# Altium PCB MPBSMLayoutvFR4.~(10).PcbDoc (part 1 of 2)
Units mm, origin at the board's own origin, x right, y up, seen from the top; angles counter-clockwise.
Board outline 131.7 x 110.39 mm, 4 copper layers (Top Layer, Power, GroundPlane, Bottom Layer), stack 2.286 mm thick; 156 components, 77 nets, 429 pads, 117 vias.
Unrouted connection lines stored in the file: 25.
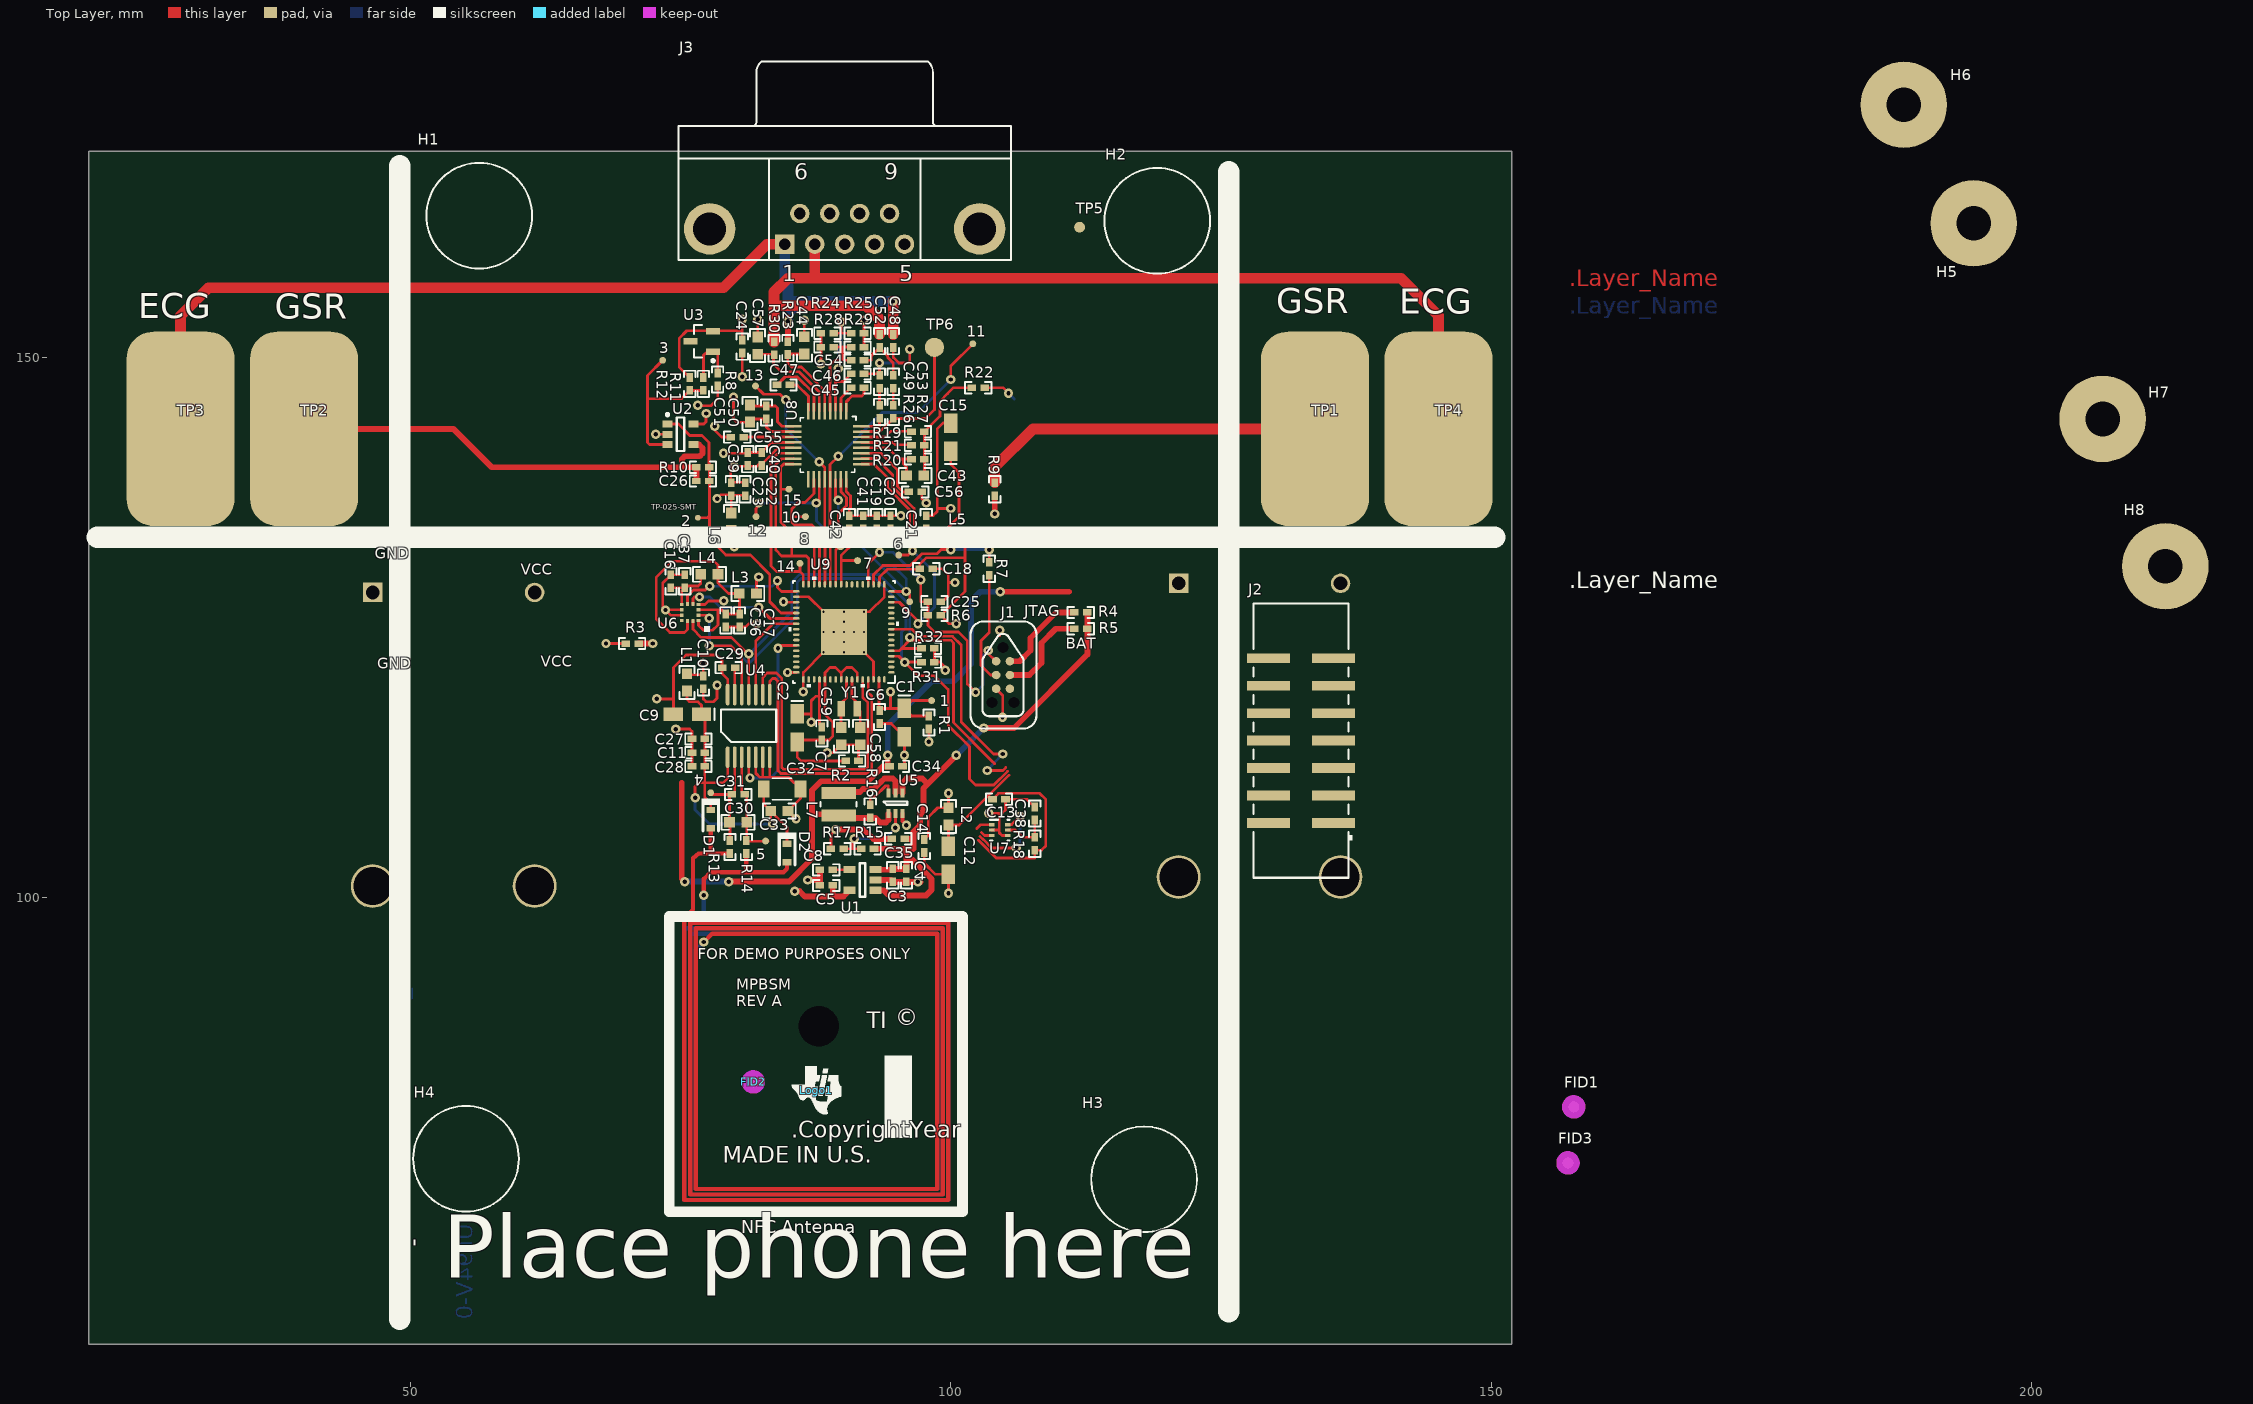
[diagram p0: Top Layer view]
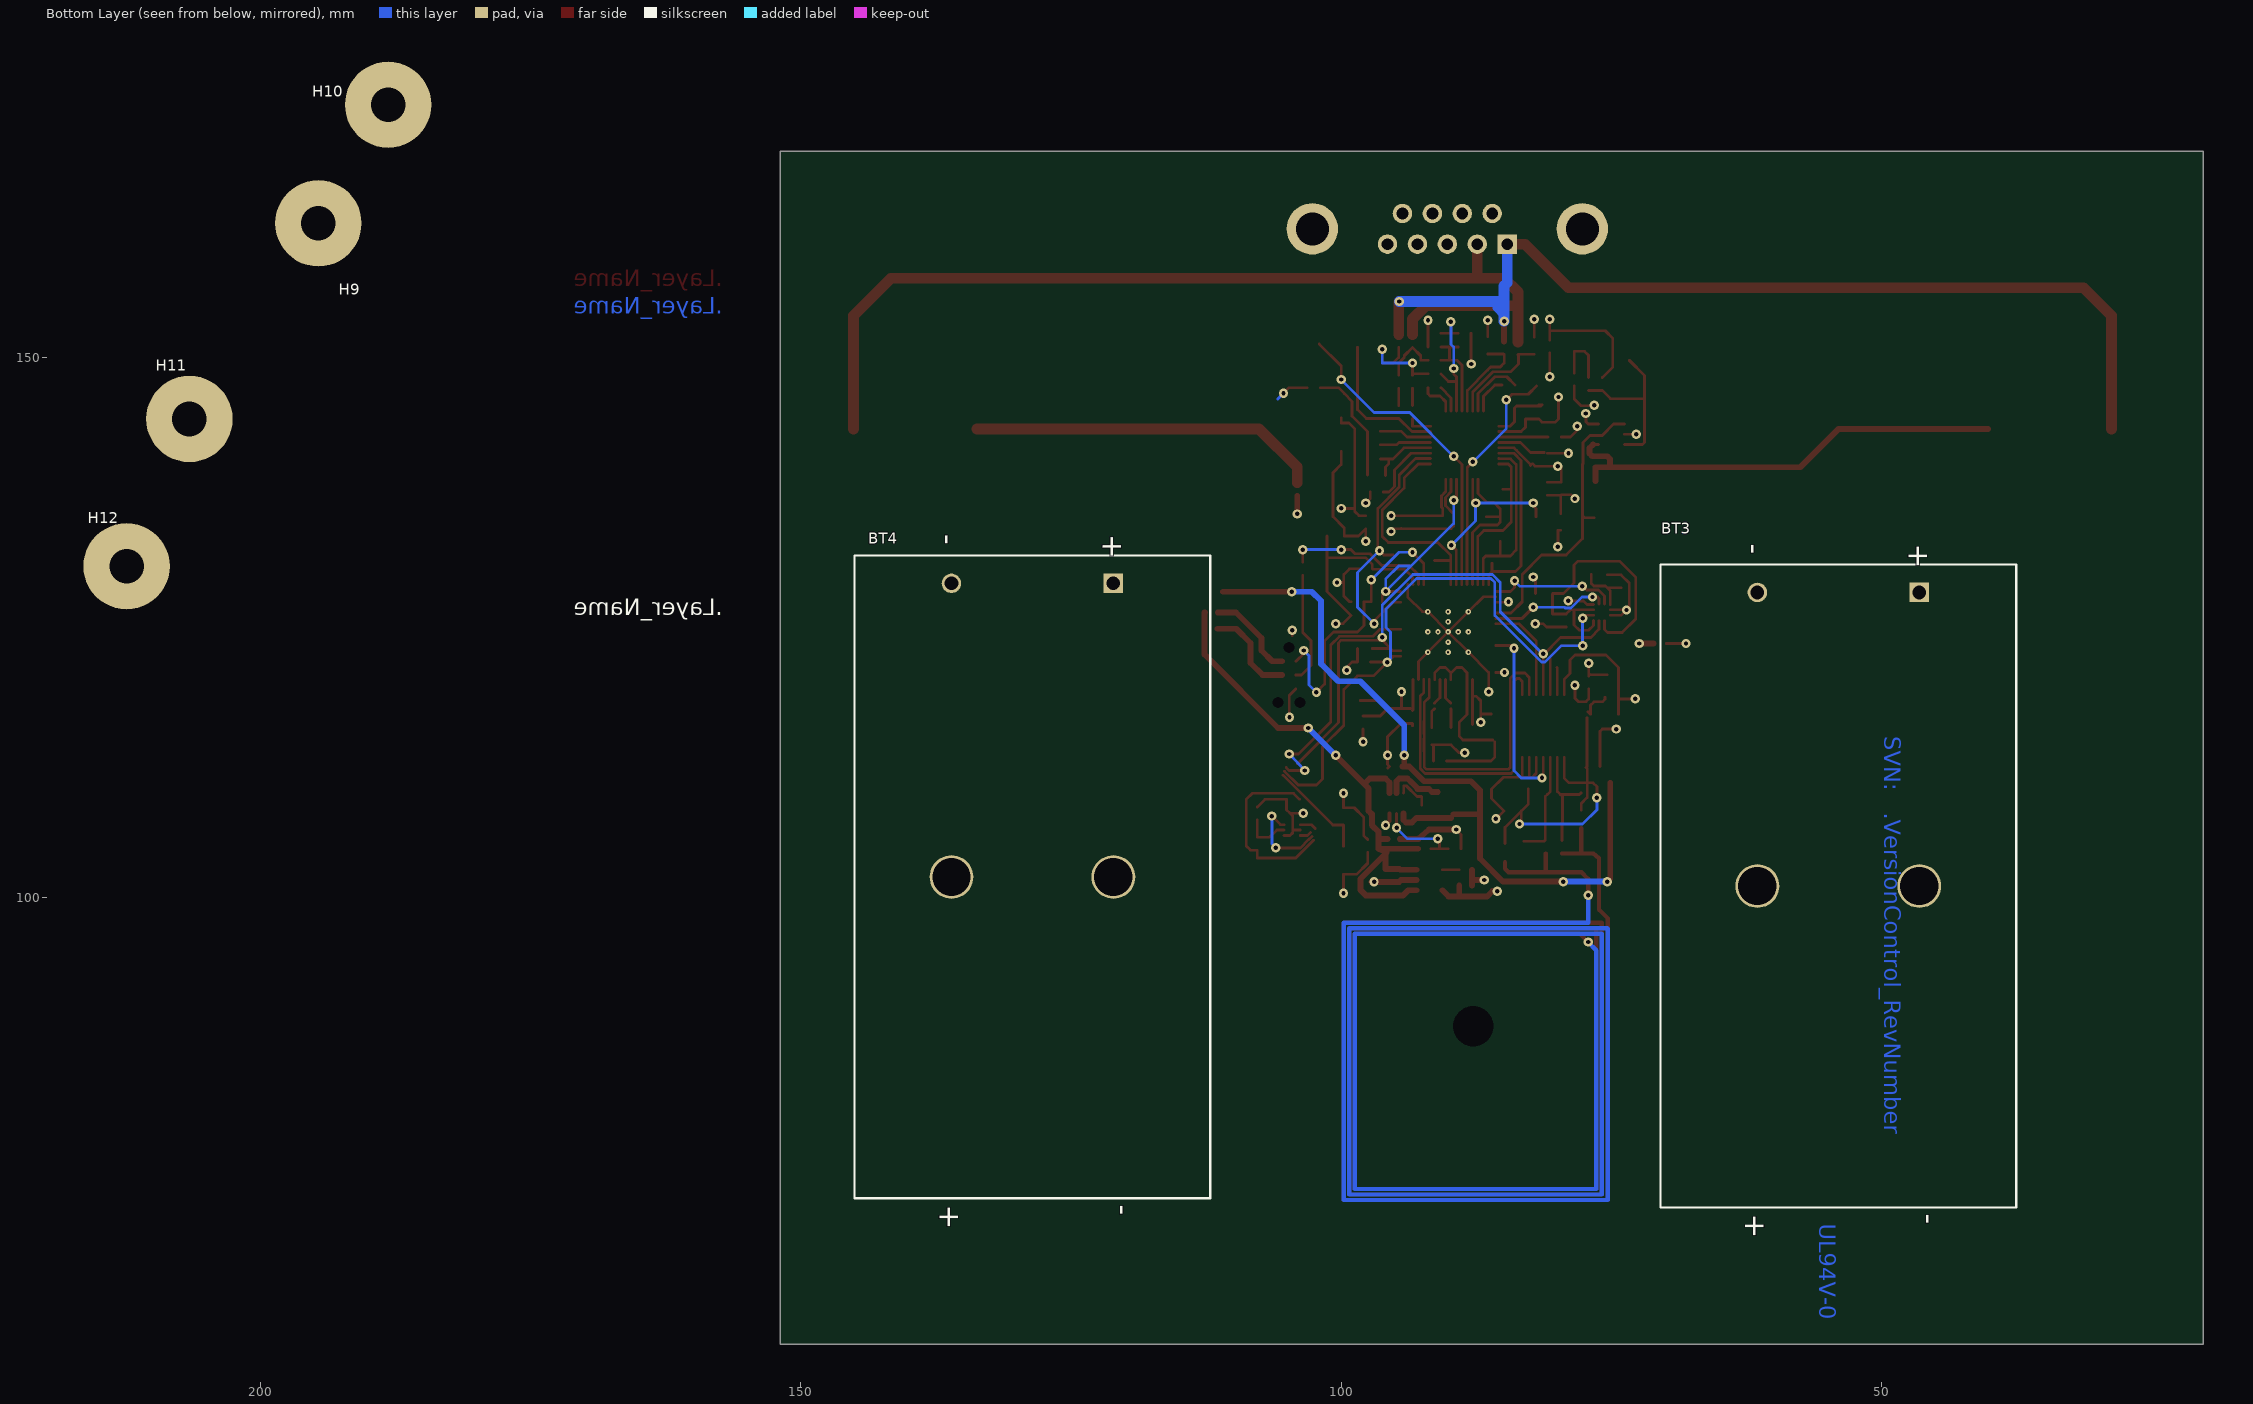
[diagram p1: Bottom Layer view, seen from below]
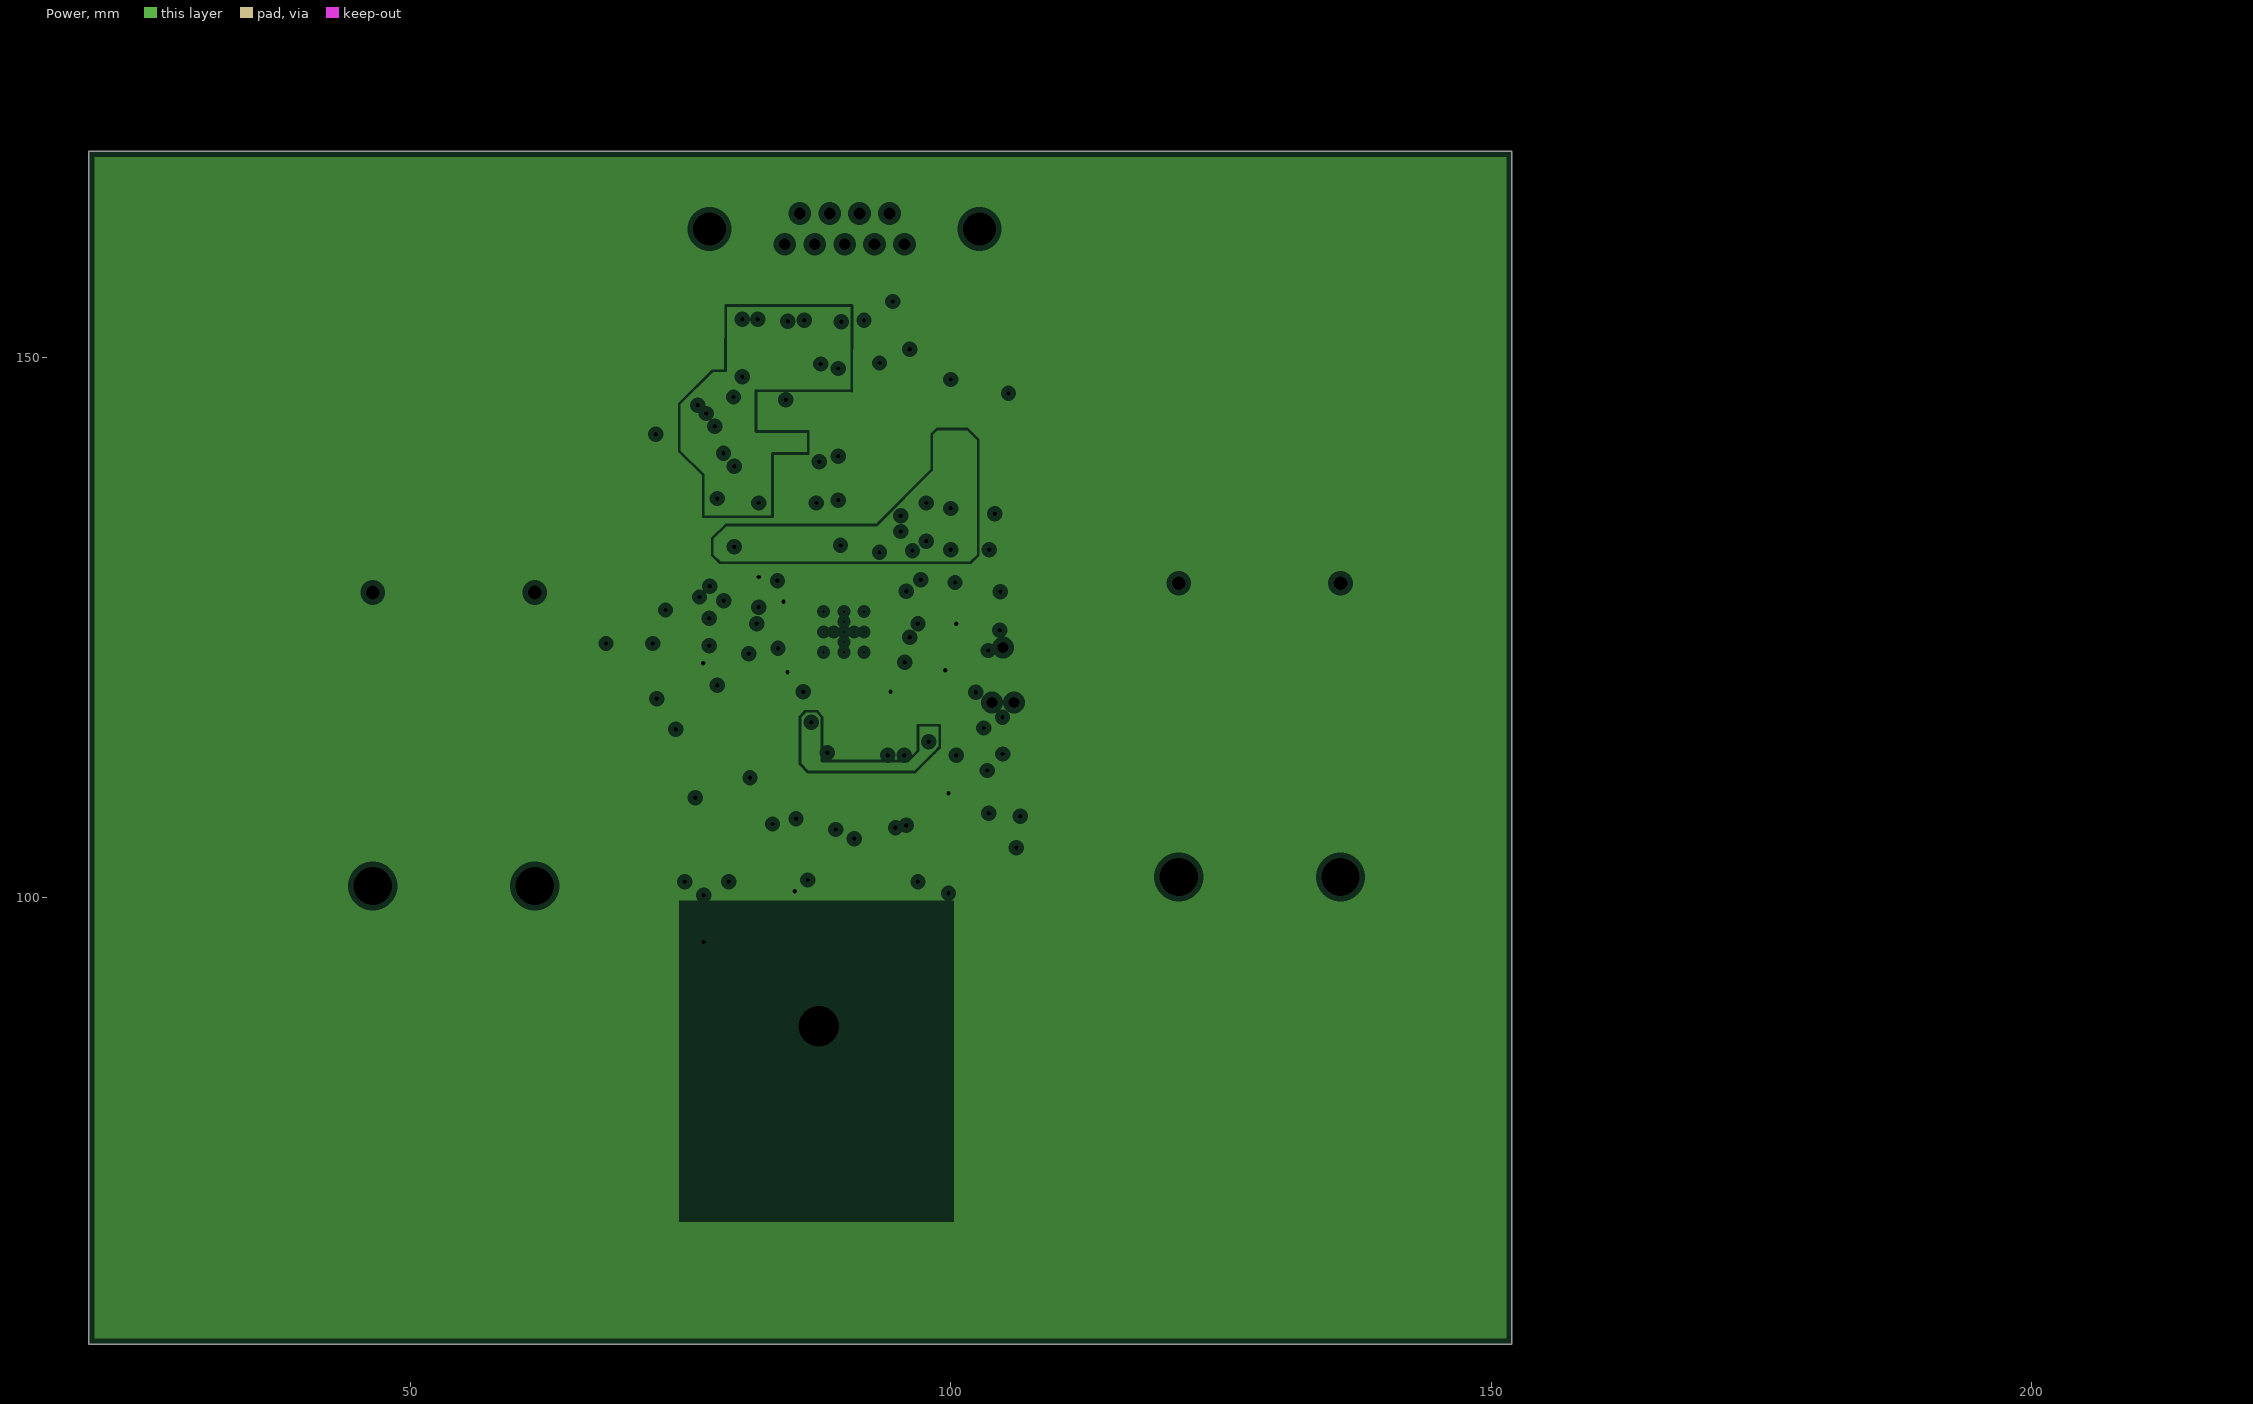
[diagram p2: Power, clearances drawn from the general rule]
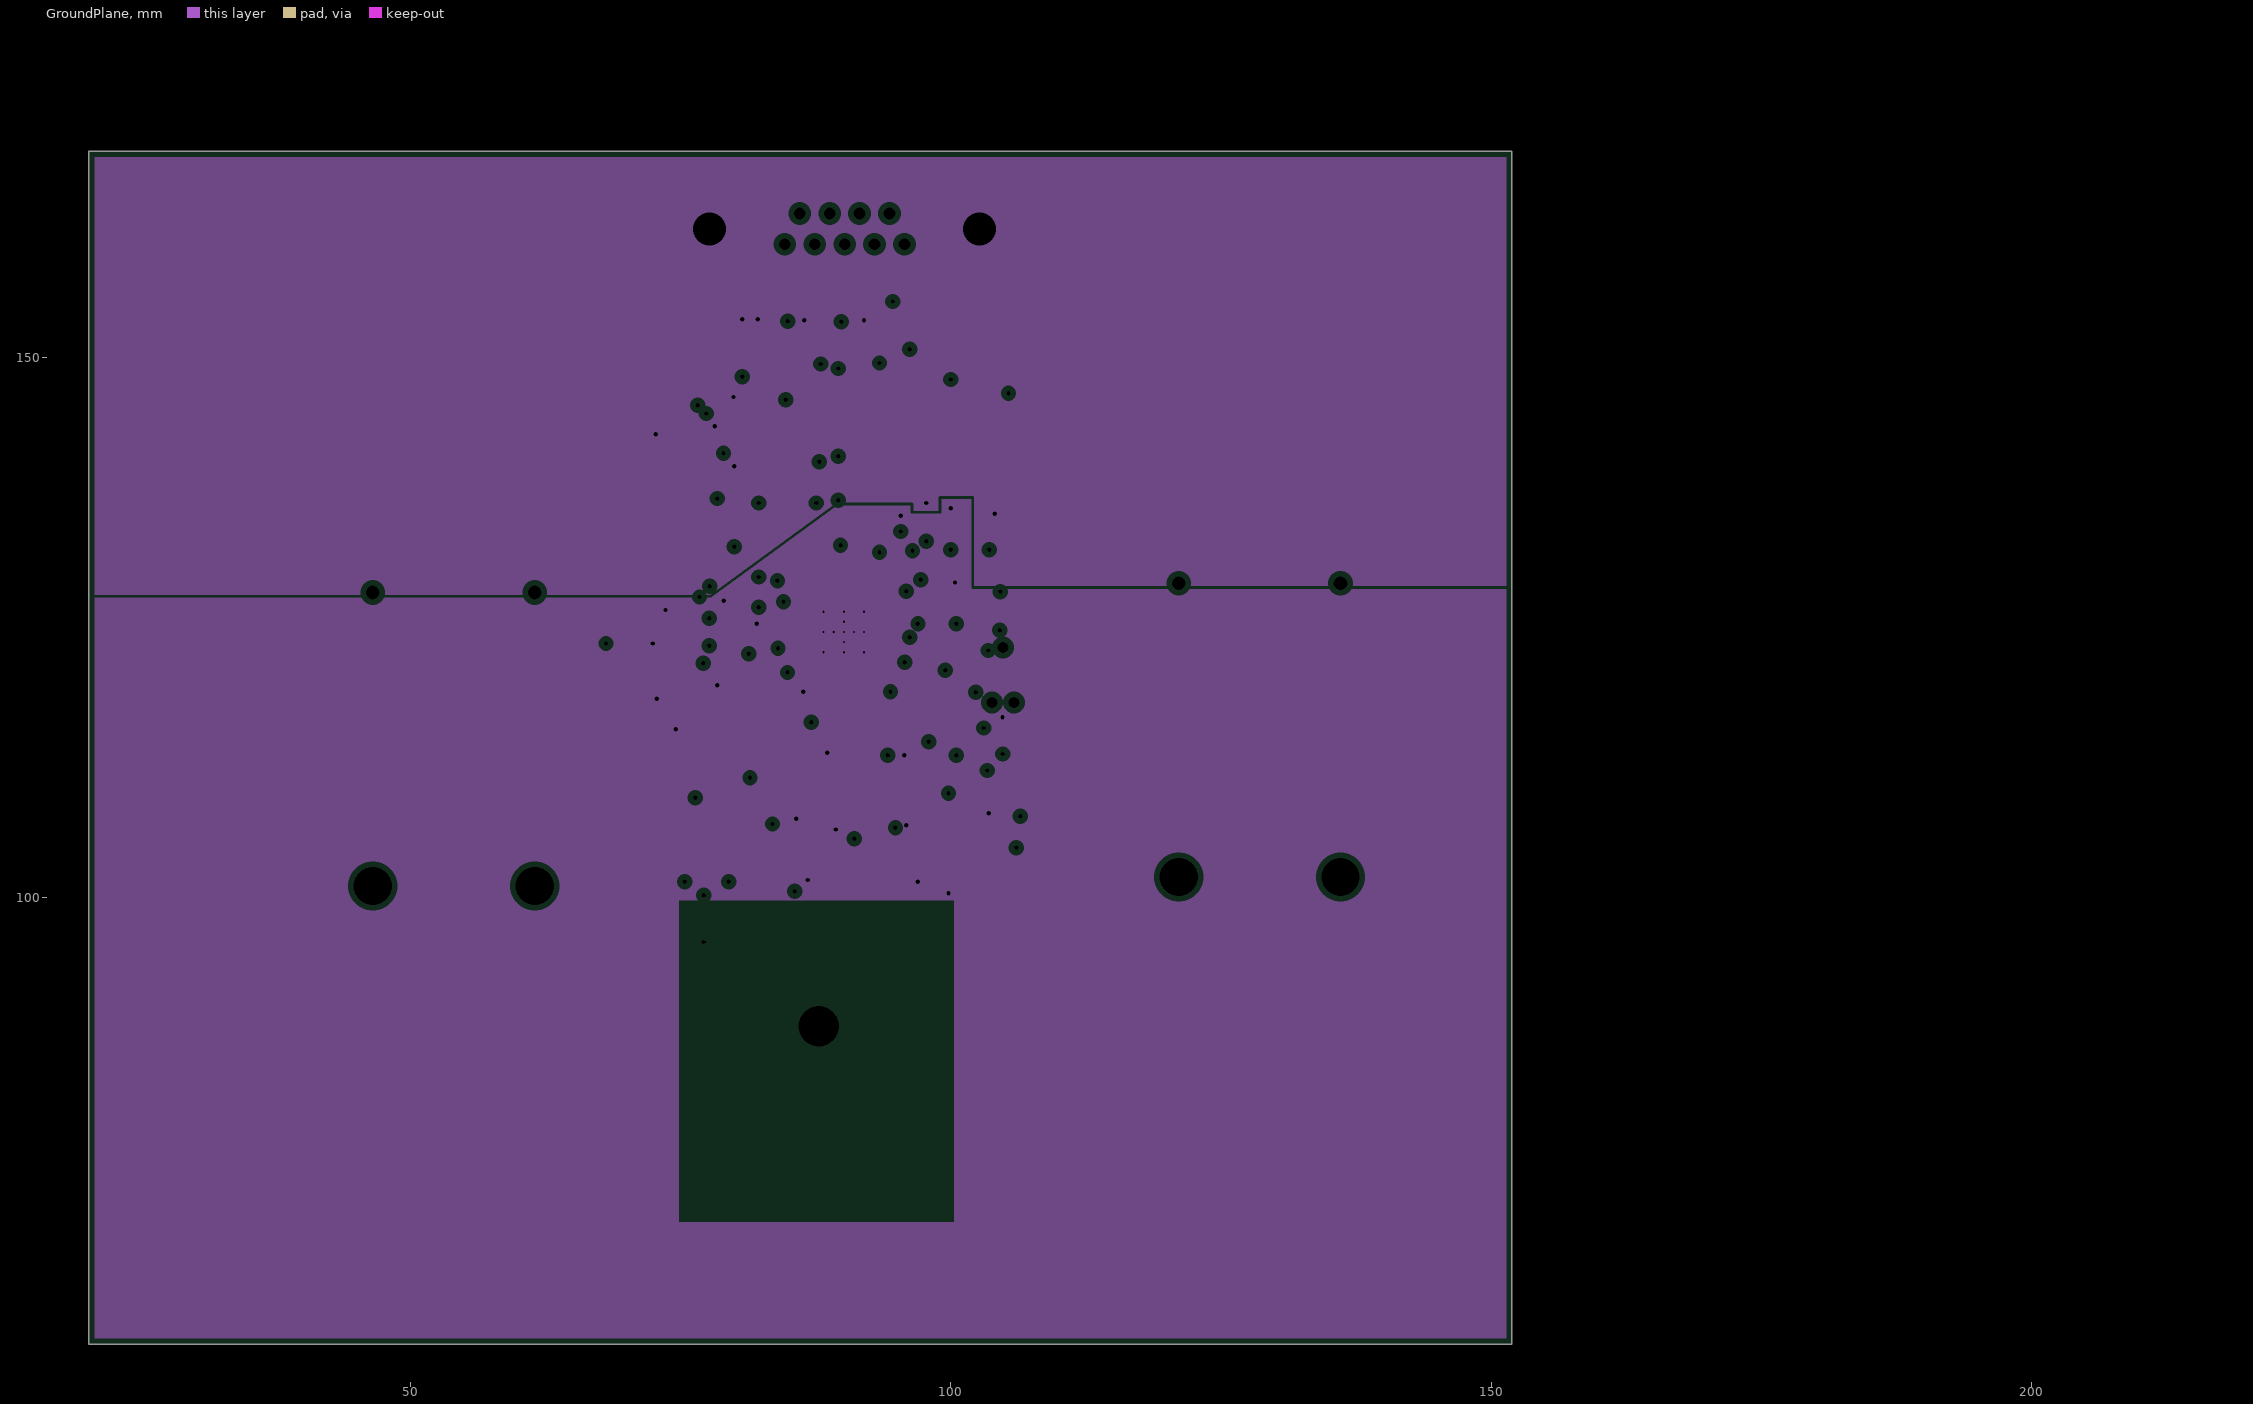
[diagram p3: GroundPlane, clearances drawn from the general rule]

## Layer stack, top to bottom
Top Solder: solder mask 0.0102, Solder Resist, Dk 3.5
Top Layer: signal copper 0.0356
Dielectric1: core 1.5037, FR-4, Dk 4.8
Power: plane copper 0.0356, net DVCC
Dielectric2: prepreg 0.32, FR-4, Dk 4.8
GroundPlane: plane copper 0.0356, net GND
Dielectric3: core 0.32, FR-4, Dk 4.8
Bottom Layer: signal copper 0.0356
Bottom Solder: solder mask 0.0102, Solder Resist, Dk 3.5

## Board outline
20.218,169.037 20.218,58.649 150.825,58.649 151.917,58.649 151.917,158.471 151.917,169.037 20.218,169.037

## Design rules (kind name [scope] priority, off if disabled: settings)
AcuteAngle [All] p1: minimum=4.50000000000000E+0001 checktracksonly=FALSE
AssemblyTestPointUsage [All] p1: valid=2
Clearance Clearance_BoardEdge_MountingHoles [OnCopper and InComponentClass('Mounting Holes') vs IsKeepOut] p1: gap=1.016
Clearance Clearance_BoardEdge_Poly [OnCopper and InPoly vs IsKeepOut] p2: gap=0.635
Clearance Clearance_BoardEdge [OnCopper and Not InComponentClass('Logo') and not InComponentClass('FiducialMark') and not InRegion(1000,500,4000,800) and Not IsKeepout vs IsKeepOut] p3: gap=1.905
Clearance Clearance_Poly [InPolygon] p4: gap=0.635
Clearance [All] p5: gap=0.1
ComponentClearance ComponentClearance_Shunt [InComponentClass('Header') vs InComponentClass('Shunt')] p1: gap=0 collisioncheckmode=3 verticalgap=0 showdistances=FALSE
ComponentClearance ComponentClearance_MountingHoles_FiducialMarks [InComponentClass('Mounting Holes') vs InComponentClass('FiducialMark')] p2: gap=1.27 collisioncheckmode=3 verticalgap=0.254 showdistances=FALSE
ComponentClearance ComponentClearance_Logo [InComponentClass('Logo')] p3: gap=1.27 collisioncheckmode=3 verticalgap=0.254 showdistances=FALSE
ComponentClearance ComponentClearance_ScrewToNut [(HasFootprint('NY PMS 440 0025 PH')) vs (HasFootprint('Keystone_1902C'))] p4: gap=0.127 collisioncheckmode=3 verticalgap=0.254 showdistances=FALSE
ComponentClearance ComponentClearance_MountingHoles [InComponentClass('Mounting Holes')] p5: gap=6.35 collisioncheckmode=3 verticalgap=2540 showdistances=FALSE
ComponentClearance ComponentClearance_SmallPassives [HasFootprint('0201*') or HasFootprint('0402*') or HasFootprint('0508') or HasFootprint('0603*') or HasFootprint('0612') or HasFootprint('0805*') or HasFootprint('0815*') or HasFootprint('0830*') or HasFootprint('1206*') or HasFootprint('1210*') or HasFootprint('1808*') or HasFootprint('1812*') or HasFootprint('1825*') or HasFootprint('2010*') or HasFootprint('2220*') or HasFootprint('2225*') or HasFootprint('2512*') or HasFootprint('2728*') or HasFootprint('3518*') vs HasFootprint('0201*') or HasFootprint('0402*') or HasFootprint('0508') or HasFootprint('0603*') or HasFootprint('0612') or HasFootprint('0805*') or HasFootprint('0815*') or HasFootprint('0830*') or HasFootprint('1206*') or HasFootprint('1210*') or HasFootprint('1808*') or HasFootprint('1812*') or HasFootprint('1825*') or HasFootprint('2010*') or HasFootprint('2220*') or HasFootprint('2225*') or HasFootprint('2512*') or HasFootprint('2728*') or HasFootprint('3518*')] p6: gap=0.508 collisioncheckmode=3 verticalgap=0.254 showdistances=FALSE
ComponentClearance ComponentClearance_THtoSMT [IsThruComponent vs IsSMTComponent] p7: gap=2.54 collisioncheckmode=3 verticalgap=0.762 showdistances=FALSE
ComponentClearance ComponentClearance_THtoTH [IsThruComponent vs IsThruComponent] p8: gap=3 collisioncheckmode=3 verticalgap=0.762 showdistances=FALSE
ComponentClearance [All] p9: gap=1.016 collisioncheckmode=3 verticalgap=0.254 showdistances=FALSE
DiffPairsRouting [All] p1: maxlimit=2.54 minlimit=0.254 mostfreqgap=0.254 toplayer_minwidth=0.381 toplayer_maxwidth=0.381 toplayer_prefwidth=0.381 bottomlayer_minwidth=0.381 bottomlayer_maxwidth=0.381 bottomlayer_prefwidth=0.381 maxuncoupledlength=25.4
FabricationTestPointUsage TestPointUsage [All] p1: valid=2 allowmultiple=FALSE
FabricationTestpoint Testpoint [All] p1: side=3 testpointundercomponent=TRUE minsize=1.016 maxsize=2.54 preferedsize=1.524 minholesize=0 maxholesize=1.016 preferedholesize=0.813 testpointgrid=0.025 allowsidetop=TRUE allowsidebottom=TRUE usegrid=TRUE gridtolerance=0
FanoutControl Fanout_LCC [IsLCC] p1: bgadir=Out bgaviamode=Centered fanoutstyle=Auto fanoutdirection=Alternating viagrid=0.025 // Fanout_LCC (Default Rule)
FanoutControl Fanout_BGA [IsBGA] p2: bgadir=Out bgaviamode=Centered fanoutstyle=Auto fanoutdirection=Alternating viagrid=0.025 // Fanout_BGA (Default Rule)
FanoutControl Fanout_Default [All] p4: bgadir=Out bgaviamode=Centered fanoutstyle=Auto fanoutdirection=Alternating viagrid=0.025 // Fanout_Default (Default Rule)
FanoutControl Fanout_Small [(CompPinCount < 5)] p5: bgadir=Out bgaviamode=Centered fanoutstyle=Auto fanoutdirection=OutThenIn viagrid=0.025 // Fanout_Small (Default Rule)
Height [All] p1: minheight=0 maxheight=55.4 prefheight=12.7
HoleSize [All] p1: absolutevalues=TRUE maxlimit=6.375 minlimit=0.1 maxpercent=80.000 minpercent=20.000
MinimumAnnularRing MinimumAnnularRing_ThermalPadVias [IsVia and InAnyComponent] p1: minimumring=0.15
MinimumAnnularRing [All] p2: minimumring=0.229
MinimumSolderMaskSliver MinimumSolderMaskSliver_Logo [InComponentClass('Logo') vs InComponentClass('Logo')] p1: minsoldermaskwidth=0.018
MinimumSolderMaskSliver [All] p2: minsoldermaskwidth=0.08
PlaneClearance [All] p1: clearance=0.508
PlaneConnect [All] p1: planeconnectstyle=Relief reliefexpansion=0.254 reliefentries=4 reliefconductorwidth=0.254 reliefairgap=0.254
PolygonConnect [All] p1: connectstyle=Relief reliefconductorwidth=0.254 reliefentries=4 polygonreliefangle="90 Angle" airgapwidth=0.254
RoutingVias ThermalPadVias [IsVia and InAnyComponent] p1: holewidth=0.2 width=0.5 viastyle="Through Hole" minholewidth=0.2 minwidth=0.5 maxholewidth=0.33 maxwidth=0.6
RoutingVias [All] p2: holewidth=0.406 width=0.864 viastyle="Through Hole" minholewidth=0.2 minwidth=0.66 maxholewidth=1.016 maxwidth=1.651
SMDToCorner [All] p1: distance=30000
SilkToSilkClearance SilkToSilkClearance_Pb-FreeLogo [(HasFootprint('Pb-Free_Overlay_Medium') OR HasFootprint('Pb-Free_Overlay_Small')) vs (HasFootprint('Pb-Free_Overlay_Medium') OR HasFootprint('Pb-Free_Overlay_Small'))] p1: silktosilkclearance=0
SilkToSilkClearance [All] p2: silktosilkclearance=0
SilkToSolderMaskClearance SilkscreenOverComponentPads [IsPad] p1: minsilkscreentomaskgap=0.127 clearancetoexposedcopper=TRUE
SolderMaskExpansion [All] p1: expansion=0.05
Width [All] p1: maxlimit=2.54 minlimit=0.152 preferedwidth=0.254 checkconnectedcopper=TRUE
14 further rules are at their usual default settings.

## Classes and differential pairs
component class Logo: Logo1
component class Designator: FID1 FID2 FID3 H1 H2 H3 H4 H5 H6 H7 H8 H9 H10 H11 H12 Logo1 ZZ1 ZZ2 ZZ3 ZZ4
component class FiducialMark: FID1 FID2 FID3
component class AssemblyNote: ZZ1 ZZ2 ZZ3 ZZ4
component class Battery: BT3 BT4 U?
component class BMA280: C36 C37 U6
component class "Boost Converter": C34 C35 L7 R15 R16 R17 U5
component class ECG: 6 7 8 9 10 11 12 13 14 15 C39 C40 C41 C42 C43 C44 C45 C46 C47 C48 C49 C50 C51 C52 C53 C54 C55 C56 C57 R19 R20 R21 R22 R23 R24 R25 R26 R27 R28 R29 R30 TP6 U8
component class GSR: 2 3 C26 R8 R9 R10 R11 R12 U2 U3
component class "JTAG SPY-BY-WIRE": C25 J1 J2 R4 R5 R6 R7
component class MSP430FR5XXX: C58 C59 R31 R32 U9 Y1
component class "Power Filtering": 1 C1 C2 C3 C4 C5 C6 C7 C8 C9 C10 C11 C12 C13 C14 C15 C16 C17 C18 C19 C20 C21 C22 C23 C24 L1 L2 L3 L4 L5 L6 R1 R2 R3 U1
component class Temperature: C38 R18 U7
component class Transponder: 4 5 C27 C28 C29 C30 C31 C32 C33 D1 D2 R13 R14 U4
component class "Analog Connector": J3
component class "Mounting Holes": H5 H6 H7 H8

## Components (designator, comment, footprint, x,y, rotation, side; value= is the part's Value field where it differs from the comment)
1 "TP-025-SMT" TP_25MIL-SMT#1 98.222,118.212 r90 top
2 "TP-025-SMT" TP_25MIL-SMT#2 76.581,135.128 r0 top
3 "TP-025-SMT" TP_25MIL-SMT#1 73.33,149.708 r0 top
4 "TP-025-SMT" TP_25MIL-SMT#1 77.77,109.676 r0 top
5 "TP-025-SMT" TP_25MIL-SMT#1 82.855,105.207 r270 top
6 "TP-025-SMT" TP_25MIL-SMT#1 95.174,131.674 r0 top
7 "TP-025-SMT" TP_25MIL-SMT#1 91.364,131.166 r0 top
8 "TP-025-SMT" TP_25MIL-SMT#1 85.268,133.198 r0 top
9 "TP-025-SMT" TP_25MIL-SMT#1 96.19,127.356 r0 top
10 "TP-025-SMT" TP_25MIL-SMT#1 86.538,135.23 r0 top
11 "TP-025-SMT" TP_25MIL-SMT#1 102.032,151.232 r0 top
12 "TP-025-SMT" TP_25MIL-SMT#1 81.966,135.23 r0 top
13 "TP-025-SMT" TP_25MIL-SMT#1 81.915,147.32 r0 top
14 "TP-025-SMT" TP_25MIL-SMT#1 86.03,130.912 r90 top
15 "TP-025-SMT" TP_25MIL-SMT#1 85.014,137.77 r0 top
BT3 "2462" Keystone_2462 53.975,114.63 r270 bottom
BT4 "2462" Keystone_2462 128.575,115.468 r270 bottom
C1 "293D106X9010A2TE3" 3216-18 95.682,116.18 r270 top
C2 "293D106X9010A2TE3" 3216-18 85.776,115.672 r270 top
C3 "C1005X5R1A104K" 0402 94.62,102.028 r270 top
C4 "C1005X5R0J105M" 0402 95.89,102.028 r270 top
C5 "C1005X5R1C225K050BC" 0402 88.473,101.092 r180 top
C6 "C1005X5R1A104K" 0402 93.396,116.688 r270 top
C7 "C1005X5R1A104K" 0402 88.062,115.164 r270 top
C8 "C1005X7R1E103K" 0402 88.468,102.54 r180 top
C9 "293D105X9016A2TE3" 3216-18 75.616,116.942 r180 top
C10 "C1005X5R1A104K" 0402 77.089,119.888 r270 top
C11 "C1005X5R1A104K" 0402 76.632,113.386 r180 top
C12 "293D106X9010A2TE3" 3216-18 99.779,103.422 r270 top
C13 "C1005X5R1A104K" 0402 104.455,109.068 r0 top
C14 "C1005X5R1A104K" 0402 97.538,104.75 r270 top
C15 "293D105X9016A2TE3" 3216-18 100,142.596 r90 top
C16 "CL05A106MQ5NUNC" 0402 74.092,129.247 r90 top
C17 "CL05A106MQ5NUNC" 0402 80.442,125.624 r270 top
C18 "C1005X5R1A104K" 0402 97.714,130.404 r0 top
C19 "C1005X5R1A104K" 0402 93.142,134.722 r90 top
C20 "C1005X5R1C225K050BC" 0402 94.412,134.722 r90 top
C21 "CL05A106MQ5NUNC" 0402 97.714,134.722 r90 top
C22 "CL05A106MQ5NUNC" 0402 80.95,137.77 r90 top
C23 "C1005X5R1A104K" 0402 79.68,137.77 r90 top
C24 "C1005X5R1A104K" 0402 80.696,150.978 r90 top
C25 "C1005X8R1H222K" 0402 98.476,127.356 r0 top
C26 "C1005X7R1E103K" 0402 77.048,138.532 r180 top
C27 "C1005X5R0J105M" 0402 76.632,114.656 r180 top
C28 "C1005X5R1A104K" 0402 76.632,112.116 r180 top
C29 "GRM155R60J474KE19D" 0402 79.426,121.26 r0 top
C30 "C1608C0G1H330J" 0603 80.31,106.941 r0 top
C31 "GRM1555C1H390JA01D" 0402 80.31,109.515 r0 top
C32 "C3216X5R1A107M160AC" 1206_190 84.374,110.023 r0 top
C33 "Used in BOM report" 0603 84.12,107.991 r0 top
C34 "CL05A106MQ5NUNC" 0402 94.92,112.116 r0 top
C35 "CL05A106MQ5NUNC" 0402 95.123,105.41 r180 top
C36 "C1005X5R1A104K" 0402 79.172,125.624 r270 top
C37 "C1005X5R1A104K" 0402 75.362,129.247 r90 top
C38 "C1005X7R1E103K" 0402 107.757,107.752 r90 top
C39 "C1005X5R1C105K050BC" 0402 81.204,140.564 r270 top
C40 "C1005X5R1A104K" 0402 82.474,140.564 r270 top
C41 "C1005X5R1C105K050BC" 0402 91.872,134.722 r90 top
C42 "C1005X5R1A104K" 0402 90.602,134.722 r90 top
C43 "C0603C152K5RACTU" 0603 96.698,139.04 r180 top
C44 "GRM1885C1H302JA01D" 0603 86.436,151.091 r90 top
C45 "GRM155R61A472KA01D" 0402 91.364,147.168 r0 top
C46 "C1005X8R1H222K" 0402 91.364,148.438 r0 top
C47 "GRM155R61A472KA01D" 0402 84.506,147.422 r180 top
C48 "C1005X5R1A104K" 0402 94.666,151.486 r270 top
C49 "C1005X8R1H222K" 0402 93.396,147.722 r90 top
C50 "C1005X5R1A104K" 0402 82.931,144.872 r270 top
C51 "C1608X5R0J106M" 0603 81.407,144.78 r270 top
C52 "C1005X5R1A104K" 0402 93.396,151.486 r270 top
C53 "C1005X8R1H222K" 0402 94.666,147.722 r90 top
C54 "C1005X8R1H222K" 0402 91.364,149.708 r0 top
C55 "C1005X5R1C105K050BC" 0402 80.234,142.596 r180 top
C56 "C1005X5R1C105K050BC" 0402 96.698,137.516 r0 top
C57 "GRM1885C1H302JA01D" 0603 82.114,151.063 r90 top
C58 "06035A100JAT2A" 0603 91.618,114.91 r270 top
C59 "06035A100JAT2A" 0603 89.865,114.91 r270 top
D1 "CDBU0130L" SOD-523F 77.77,107.229 r270 top
D2 "CDBU0130L" SOD-523F 84.836,104.089 r270 top
FID1 "Fiducial" Fiducial10-20 157.658,80.594 r0 top
FID2 "Fiducial" Fiducial10-20 81.712,82.906 r0 top
FID3 "Fiducial" Fiducial10-20 157.124,75.413 r0 top
H1 "SJ61A2" Bumpon_SJ61A2 56.337,163.093 r0 top
H2 "SJ61A2" Bumpon_SJ61A2 119.101,162.611 r0 top
H3 "SJ61A2" Bumpon_SJ61A2 117.881,73.889 r0 top
H4 "SJ61A2" Bumpon_SJ61A2 55.118,75.794 r0 top
H5 "NY PMS 440 0025 PH" "NY PMS 440 0025 PH" 194.666,162.382 r90 top
H6 "NY PMS 440 0025 PH" "NY PMS 440 0025 PH" 188.214,173.355 r90 top
H7 "NY PMS 440 0025 PH" "NY PMS 440 0025 PH" 206.604,144.272 r90 top
H8 "NY PMS 440 0025 PH" "NY PMS 440 0025 PH" 212.421,130.638 r90 top
H9 "1902C" Keystone_1902C 194.665,162.376 r90 bottom
H10 "1902C" Keystone_1902C 188.239,173.33 r90 bottom
H11 "1902C" Keystone_1902C 206.604,144.272 r90 bottom
H12 "1902C" Keystone_1902C 212.42,130.632 r180 bottom
J1 "TC2030-MCP-NL" TC2030-MCP-NL 104.826,120.574 r180 top
J2 "61201420621" Wurth_61201420621 132.41,114.503 r180 top
J3 "182-009-213R171" NORCOMP_182-009-213R171 90.17,171.374 r0 top
L1 "BLM18HG601SN1D" 0603 75.565,119.888 r270 top
L2 "BLM18HG601SN1D" 0603 99.779,107.486 r270 top
L3 "BLM18HG601SN1D" 0603 81.204,128.118 r180 top
L4 "BLM18HG601SN1D" 0603 77.648,129.896 r0 top
L5 "BLM18HG601SN1D" 0603 100.508,133.452 r180 top
L6 "BLM18HG601SN1D" 0603 79.68,134.772 r90 top
L7 "EPL3015-472MLB" EPL3015 89.611,108.61 r90 top
Logo1 "Texas Instruments" TI_Symbol_Overlay_Small 87.554,82.144 r0 top
R1 "ERJ-2GE0R00X" 0402 97.968,116.18 r270 top
R2 "ERJ-2GE0R00X" 0402 90.856,112.624 r180 top
R3 "ERJ-2GE0R00X" 0402 70.494,123.489 r180 top
R4 "ERJ-2GE0R00X" 0402 112.014,126.365 r0 top
R5 "ERJ-2GE0R00X" 0402 112.033,124.861 r0 top
R6 "CRCW040247K0JNED" 0402 98.476,126.086 r0 top
R7 "ERJ-2GE0R00X" 0402 103.556,130.404 r90 top
R8 "CRCW040221K5FKED" 0402 78.41,147.93 r270 top
R9 "CRCW040210K0FKED" 0402 104.064,137.77 r90 top
R10 "ERJ-2RKF1004X" 0402 77.048,139.802 r0 top
R11 "CRCW040211K8FKED" 0402 77.094,147.517 r90 top
R12 "CRCW04028K06FKED" 0402 75.824,147.517 r270 top
R13 "ERJ-2GE0R00X" 0402 79.548,104.655 r270 top
R14 "ERJ-2GE0R00X" 0402 81.072,104.655 r270 top
R15 "ERJ-2RKF1004X" 0402 92.288,104.496 r0 top
R16 "ERJ-2GE0R00X" 0402 92.532,107.95 r90 top
R17 "ERJ-2RKF2003X" 0402 89.494,104.496 r0 top
R18 "CRCW04024K99FKED" 0402 107.757,104.958 r270 top
R19 "ERJ-2GE0R00X" 0402 96.952,143.104 r0 top
R20 "ERJ-2RKF1004X" 0402 96.952,140.564 r0 top
R21 "ERJ-2RKF1003X" 0402 96.952,141.834 r0 top
R22 "ERJ-2RKF1003X" 0402 102.54,147.168 r0 top
R23 "CRCW040251K1FKED" 0402 84.912,150.837 r270 top
R24 "CRCW040210M0FKED" 0402 88.57,152.202 r180 top
R25 "CRCW040210M0FKED" 0402 91.364,152.202 r180 top
R26 "CRCW040240K2FKED" 0402 93.396,144.928 r270 top
R27 "CRCW040240K2FKED" 0402 94.666,144.928 r270 top
R28 "CRCW040210M0FKED" 0402 88.57,150.932 r180 top
R29 "CRCW040210M0FKED" 0402 91.364,150.932 r180 top
R30 "CRCW040251K1FKED" 0402 83.638,150.809 r270 top
R31 "CRCW04023K30JNED" 0402 97.876,121.768 r180 top
R32 "CRCW04023K30JNED" 0402 97.876,123.038 r180 top
TP1 "TESTPOINT" TP_SM_1MM#1 133.706,143.358 r0 top
TP2 "TESTPOINT" TP_SM_1MM#2 40.132,143.358 r90 top
TP3 "TESTPOINT" TP_SM_1MM#2 28.702,143.358 r90 top
TP4 "TESTPOINT" TP_SM_1MM#2 145.136,143.358 r90 top
TP5 "TESTPOINT" TP_SM_1MM#3 111.912,162.027 r90 top
TP6 "Pogo Pad" PogoPad 98.476,150.901 r0 top locked
U1 "TPS73030DBVR" DBV0005A_N 91.821,101.6 r180 top
U2 "LMP2231AMFE" MF05A_L 74.97,142.85 r0 top
U3 "LM4041AIM3-1.2" MF03A_N 76.937,151.46 r180 top
U4 "RF430CL331HCPW" PW0014A_M 81.287,115.864 r90 top
U5 "TPS61220DCK" DCK0006A_N 94.869,108.712 r90 top
U6 "BMA280" LGA-12P 75.87,126.361 r90 top
U7 "TMP112AIDRL" DRL0006A 104.529,106.221 r0 top
U8 "ADS1292RIPBS" PBS0032A_N 88.57,141.853 r270 top
U9 "MSP430FR5889IRGCR" RGC0064B 90.094,124.562 r180 top
Y1 "FC-12M 32.7680KA-A3" Epson_FC-12M 90.602,117.45 r0 top
ZZ1 "This Assembly Note is for PCB labels only" AssemblyNoteLabel 35.992,195.631 r0 top
ZZ2 "These assemblies are ESD sensitive, ESD precautions shall be observed." AssemblyNote 35.992,192.865 r0 top
ZZ3 "These assemblies must be clean and free from flux and all contaminants. Use of no clean flux is not acceptable." AssemblyNote 35.992,190.616 r0 top
ZZ4 "These assemblies must comply with workmanship standards IPC-A-610 Class 2, unless otherwise specified." AssemblyNote 35.992,188.366 r0 top

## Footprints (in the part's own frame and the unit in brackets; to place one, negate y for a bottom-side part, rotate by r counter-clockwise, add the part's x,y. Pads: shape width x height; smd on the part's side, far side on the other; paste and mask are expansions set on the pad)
0402 [mm] "0402 from SM-752 data"
  rect 0.8x0.6 smd: 1(-0.6,0) 2(0.6,0)
  silkscreen extent -1.22,-0.52 1.22,0.52, body extent -0.55,-0.3 0.55,0.3, height 0.6
0603 [mm] "0603 from SM-752 data"
  rect 1x0.95 smd: 1(-0.8,0) 2(0.8,0)
  silkscreen extent -1.52,-0.69 1.52,0.69, body extent -0.87,-0.47 0.87,0.47, height 0.85
1206_190 [mm] "1206_190"
  rect 1.1x1.6 smd: 1(-1.7,0) 2(1.7,0)
  silkscreen extent -0.9,-1 0.9,1, body extent -1.75,-0.95 1.75,0.95, height 1.9
3216-18 [mm] "Medium density IPC, based on Kemet T495 dimensions"
  rect 1.8x1.25 smd: 1(-1.3,0) 2(1.3,0)
  silkscreen extent -2.49,-0.54 -2.49,0.54, body extent -1.7,-0.9 1.7,0.9, height 1.8
AssemblyNote [mm] "Assembly Note"
AssemblyNoteLabel [mm] "Assembly Note for PCB Labels"
Bumpon_SJ61A2 [mil] "3M Hemispherical Bumpon transparent"
  round 1 on Mech3: 0(0,0)
  silkscreen extent -192,-192 192,192, body extent -191,-192 193,192, height 250
DBV0005A_N [mm] "SOT23, 5-Leads, Body 2.9x1.6mm, Pitch 0.95mm, Lead Span 2.8mm, IPC Medium Density"
  rect 1.1x0.65 smd: 1(-1.2,0.95) 2(-1.2,0) 3(-1.2,-0.95) 4(1.2,-0.95) 5(1.2,0.95)
  silkscreen extent -0.25,-1.55 0.25,1.55, body extent -1.42,-1.46 1.42,1.46, height 1.08
DCK0006A_N [mm] "SOT23, 6-Leads, Body 2x1.3mm, Pitch 0.65mm, Lead Span 2.1mm, IPC Medium Density"
  rect 0.85x0.4 smd: 1(-0.95,0.65) 2(-0.95,0) 3(-0.95,-0.65) 4(0.95,-0.65) 5(0.95,0) 6(0.95,0.65)
  silkscreen extent -0.15,-1.1 0.15,1.1, body extent -1.14,-1 1.14,1, height 0.94
DRL0006A [mm] "SOTFL, 6-Flat Leads, Body 1.2x1.6x0.6mm, Pitch 0.5mm, TI recommended"
  rect 0.5x0.3 smd: 1(-0.75,0.5) 2(-0.75,0) 3(-0.75,-0.5) 4(0.75,-0.5) 5(0.75,0) 6(0.75,0.5)
  silkscreen extent -0.9,-0.95 0.9,0.95, body extent -0.85,-0.85 0.85,0.85, height 0.62
EPL3015 [mm] "COILCRAFT"
  rect 1.12x3.2 smd: 1(-1.04,0) 2(1.04,0)
  silkscreen extent -0.22,-1.65 0.23,1.68, body extent -1.6,-1.6 1.6,1.6, height 1.55
Epson_FC-12M [mm] "Epson"
  rect 0.7x1.4 smd: 1(-0.75,0) 2(0.75,0)
  body extent -1.05,-0.63 1.05,0.63, height 0.6
Fiducial10-20 [mm]
  round 1 smd mask+0.5: 1(0,0)
  Top Layer keep-out circle w1.178: c0,0 r0.5
Keystone_1902C [mil] "Hex Standoff, 4-40 threaded, nylon"
  round 1 on Mech4: 0(0,0)
  body extent -145,-126 146,126, height 501
Keystone_2462 [mm] "2x AA Battery Holder, Through-hole mount"
  rect 1.8x1.8 hole 1.27: 1(-13.59,7.495)
  round 1.8 hole 1.27: 2(-13.59,-7.495)
  round 4.05 hole 3.55: 3(13.59,-7.495) 4(13.59,7.495)
  silkscreen extent -16.18,-16.46 43.33,16.46, body extent -16.31,-16.46 43.4,16.46, height 16
LGA-12P [mm]
  rect 0.3x0.35 smd mask+0.05: 1(-0.75,-0.775) 2(-0.25,-0.775) 3(0.25,-0.775) 4(0.75,-0.775) 7(0.75,0.775) 8(0.25,0.775) 9(-0.25,0.775) 10(-0.75,0.775)
  rect 0.35x0.3 smd mask+0.05: 5(0.775,-0.25) 6(0.775,0.25) 11(-0.775,0.25) 12(-0.775,-0.25)
  silkscreen extent -1.8,-1.8 -1.29,-1.3
MF03A_N [mm] "SOT23, 3-Leads, Body 2.9x1.3mm, Pitch 0.95mm, Lead Span 2.4mm, IPC Medium Density"
  rect 1.3x0.6 smd: 1(-1.05,0.95) 2(-1.05,-0.95) 3(1.05,0)
  silkscreen extent -1.18,-1.5 0.7,1.92, body extent -0.7,-1.5 0.7,1.5, height 1.12
MF05A_L [mm] "SOT23, 5-Leads, Body 2.9x1.6mm, Pitch 0.95mm, Lead Span 2.8mm, IPC High Density"
  rect 0.9x0.65 smd: 1(-1.2,0.95) 2(-1.2,0) 3(-1.2,-0.95) 4(1.2,-0.95) 5(1.2,0.95)
  silkscreen extent -1.32,-1.55 0.35,1.95, body extent -0.9,-1.55 0.9,1.55, height 1.19
NORCOMP_182-009-213R171 [mm] "Connector; D Subminiature 9 Position; Right Angle"
  rect 1.8x1.8 hole 1.092: 1(-5.54,-10.92)
  round 1.8 hole 1.092: 2(-2.77,-10.92) 3(0,-10.92) 4(2.77,-10.92) 5(5.54,-10.92) 6(-4.155,-8.08) 7(-1.385,-8.08) 8(1.385,-8.08) 9(4.155,-8.08)
  round 4.76 hole 3.05: 10(-12.495,-9.5) 11(12.495,-9.5)
  silkscreen extent -15.4,-12.4 15.4,6, body extent -15.41,-12.98 15.41,6.1, height 12.55
"NY PMS 440 0025 PH" [mm] "4-40 nylon screw and mounting hole"
  round 8 hole 3.2: 1(0,0)
  body extent -3.3,-3.3 3.3,3.3, height 2.69
PBS0032A_N [mil]
  rect 60x9 smd: 1(-124,68.9) 2(-124,49.21) 3(-124,29.53) 4(-124,9.84) 5(-124,-9.84) 6(-124,-29.53) 7(-124,-49.21) 8(-124,-68.9) 17(124,-68.9) 18(124,-49.21) 19(124,-29.53) 20(124,-9.84) 21(124,9.84) 22(124,29.53) 23(124,49.21) 24(124,68.9)
  rect 9x60 smd: 9(-68.9,-124) 10(-49.21,-124) 11(-29.53,-124) 12(-9.84,-124) 13(9.84,-124) 14(29.53,-124) 15(49.21,-124) 16(68.9,-124) 25(68.9,124) 26(49.21,124) 27(29.53,124) 28(9.84,124) 29(-9.84,124) 30(-29.53,124) 31(-49.21,124) 32(-68.9,124)
  silkscreen extent -104,-100 100,104, body extent -140,-140 140,140, height 48
PogoPad [mil] "No Solder Paste"
  round 70 smd paste-35: 1(0,0)
PW0014A_M [mm] "TSOP, 14-Leads, Body 5x4.4mm, Pitch 0.65mm, IPC Low Density"
  oval 2x0.35 smd: 1(-2.9,1.95) 2(-2.9,1.3) 3(-2.9,0.65) 4(-2.9,0) 5(-2.9,-0.65) 6(-2.9,-1.3) 7(-2.9,-1.95) 8(2.9,-1.95) 9(2.9,-1.3) 10(2.9,-0.65) 11(2.9,0) 12(2.9,0.65) 13(2.9,1.3) 14(2.9,1.95)
  silkscreen extent -1.5,-2.55 1.53,2.55, body extent -3.21,-2.5 3.21,2.5, height 0.98
RGC0064B [mm]
  oval 0.6x0.24 smd mask+0.07: 1(-4.4,3.75) 2(-4.4,3.25) 3(-4.4,2.75) 4(-4.4,2.25) 5(-4.4,1.75) 6(-4.4,1.25) 7(-4.4,0.75) 8(-4.4,0.25) 9(-4.4,-0.25) 10(-4.4,-0.75) 11(-4.4,-1.25) 12(-4.4,-1.75) 13(-4.4,-2.25) 14(-4.4,-2.75) 15(-4.4,-3.25) 16(-4.4,-3.75) 33(4.4,-3.75) 34(4.4,-3.25) 35(4.4,-2.75) 36(4.4,-2.25) 37(4.4,-1.75) 38(4.4,-1.25) 39(4.4,-0.75) 40(4.4,-0.25) 41(4.4,0.25) 42(4.4,0.75) 43(4.4,1.25) 44(4.4,1.75) 45(4.4,2.25) 46(4.4,2.75) 47(4.4,3.25) 48(4.4,3.75)
  oval 0.24x0.6 smd mask+0.07: 17(-3.751,-4.4) 18(-3.251,-4.4) 19(-2.751,-4.4) 20(-2.251,-4.4) 21(-1.75,-4.4) 22(-1.25,-4.4) 23(-0.75,-4.4) 24(-0.25,-4.4) 25(0.25,-4.4) 26(0.75,-4.4) 27(1.25,-4.4) 28(1.75,-4.4) 29(2.251,-4.4) 30(2.751,-4.4) 31(3.251,-4.4) 32(3.751,-4.4) 49(3.751,4.4) 50(3.251,4.4) 51(2.751,4.4) 52(2.251,4.4) 53(1.75,4.4) 54(1.25,4.4) 55(0.75,4.4) 56(0.25,4.4) 57(-0.25,4.4) 58(-0.75,4.4) 59(-1.25,4.4) 60(-1.75,4.4) 61(-2.251,4.4) 62(-2.751,4.4) 63(-3.251,4.4) 64(-3.751,4.4)
  rect 4.25x4.25 smd paste-2.112: 65(0,0)
  silkscreen extent -5.1,-5.1 5.1,5.1, body extent -4.57,-4.57 4.57,4.57, height 1.01
SOD-523F [mm] "COMCHIP"
  rect 0.6x0.8 smd paste-0.05: 1(-0.85,0) 2(0.85,0)
  silkscreen extent -1.92,-0.87 1.1,0.88, body extent -0.9,-0.5 0.9,0.5, height 0.85
TC2030-MCP-NL [mil] "TAG-CONNECT"
  round 31 smd paste-16: 1(-25,-50) 2(25,-50) 3(-25,0) 4(25,0) 5(-25,50) 6(25,50)
  round 25 hole 39 unplated: MH1(0,-100) MH2(-40,100) MH3(40,100)
  silkscreen extent -122,-195 118,195
TI_Symbol_Overlay_Small [mm]
  silkscreen extent -2.3,-2.23 2.3,2.24
TP_25MIL-SMT#1 [mm]
  round 0.635 smd mask-0.064: 1(0,0)
TP_25MIL-SMT#2 [mm]
  round 0.535 smd mask-0.064: 1(0,0)
TP_SM_1MM#1 [mm] "1mm Test Point, SMT"
  rrect50% 10x18 smd paste-0.5: 1(0,0)
TP_SM_1MM#2 [mm] "1mm Test Point, SMT"
  rrect50% 18x10 smd paste-0.5: 1(0,0)
TP_SM_1MM#3 [mm] "1mm Test Point, SMT"
  round 1 smd paste-0.5: 1(0,0)
Wurth_61201420621 [mm] "Header, 2.54mm, 7x2, SMT"
  rect 4x0.9 smd: 1(-3,7.62) 2(3,7.62) 3(-3,5.08) 4(3,5.08) 5(-3,2.54) 6(3,2.54) 7(-3,0) 8(3,0) 9(-3,-2.54) 10(3,-2.54) 11(-3,-5.08) 12(3,-5.08) 13(-3,-7.62) 14(3,-7.62)
  silkscreen extent -4.75,-12.7 4.4,12.7, body extent -4.75,-12.7 4.75,12.7, height 10.43

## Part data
1 2 3 4 5 6 7 8 9 10 11 12 13 14 15: "Test Point, O.025\""
BT3 BT4: "2x AA Battery Holder, Through-hole mount"
C1 C2 C12: "CAP, TA, 10 µF, 10 V, +/- 10%, 3.4 ohm, SMD"
C3 C6 C7 C10 C11 C13 C14 C18 C19 C23 C24 C28 C36 C37 C40 C42 C48 C50 C52: "CAP, CERM, 0.1 µF, 10 V, +/- 10%, X5R, 0402"
C4 C27: "CAP, CERM, 1 µF, 6.3 V, +/- 20%, X5R, 0402"
C5 C20: "CAP, CERM, 2.2 µF, 16 V, +/- 10%, X5R, 0402"
C8 C26 C38: "CAP, CERM, 0.01 µF, 25 V, +/- 10%, X7R, 0402"
C9 C15: "CAP, TA, 1 µF, 16 V, +/- 10%, 9.3 ohm, SMD"
C16 C17 C21 C22 C34 C35: "CAP, CERM, 10 µF, 6.3 V, +/- 20%, X5R, 0402"
C25 C46 C49 C53 C54: "CAP, CERM, 2200 pF, 50 V, +/- 10%, X8R, 0402"
C29: "CAP, CERM, 0.47 µF, 6.3 V, +/- 10%, X5R, 0402"
C30: "CAP, CERM, 33 pF, 50 V, +/- 5%, C0G/NP0, 0603"
C31: "CAP, CERM, 39pF, 50V, +/-5%, C0G/NP0, 0402"
C32: "CAP, CERM, 100 µF, 10 V, +/- 20%, X5R, 1206_190"
C33: library part Capacitor, "CAP, CERM, xxxF, xxV, [TempCo], xx%, [PackageReference]"
C39 C41 C55 C56: "CAP, CERM, 1 µF, 16 V, +/- 10%, X5R, 0402"
C43: "CAP, CERM, 1500 pF, 50 V, +/- 10%, X7R, 0603"
C44 C57: "CAP, CERM, 3000 pF, 50 V, +/- 5%, C0G/NP0, 0603"
C45 C47: "CAP, CERM, 4700 pF, 10 V, +/- 10%, X5R, 0402"
C51: "CAP, CERM, 10 µF, 6.3 V, +/- 20%, X5R, 0603"
C58 C59: "CAP, CERM, 10 pF, 50 V, +/- 5%, C0G/NP0, 0603"
D1 D2: "Diode, Schottky, 35V, 0.1A, SOD-523F"
FID1 FID2 FID3: "Fiducial mark.  There is nothing to buy or mount."
H1 H2 H3 H4: "Bumpon, Hemisphere, 0.375 X 0.235, Black"
H5 H6 H7 H8: "Machine Screw, Round, #4-40 x 1/4, Nylon, Philips panhead"
H9 H10 H11 H12: "Standoff, Hex, 0.5\"L #4-40 Nylon"
J1: "Footprint for TC2030-MCP-NL"
J2: "Header(Shrouded), 2.54mm, 7x2, Gold, Black, SMT"
J3: "CONN DB9 FEMALE R/A SOLDER TH"
L1 L2 L3 L4 L5 L6: "Ferrite Bead, 600 ohm @ 100MHz, 0.2A, 0603"
L7: "Inductor, Shielded, Ferrite, 4.7uH, 1.2A, 0.14 ohm, SMD"
Logo1: library part TI_Logo, "Texas Instrument Corporate Signature"
R1 R2 R3 R4 R5 R7 R13 R14 R16 R19: "RES, 0, 5%, 0.063 W, 0402"
R6: "RES, 47 k, 5%, 0.063 W, 0402"
R8: "RES, 21.5 k, 1%, 0.063 W, 0402"
R9: "RES, 10.0 k, 1%, 0.063 W, 0402"
R10 R15 R20: "RES, 1.00 M, 1%, 0.1 W, 0402"
R11: "RES, 11.8 k, 1%, 0.063 W, 0402"
R12: "RES, 8.06 k, 1%, 0.063 W, 0402"
R17: "RES, 200 k, 1%, 0.1 W, 0402"
R18: "RES, 4.99 k, 1%, 0.063 W, 0402"
R21 R22: "RES, 100 k, 1%, 0.1 W, 0402"
R23 R30: "RES, 51.1 k, 1%, 0.063 W, 0402"
R24 R25 R28 R29: "RES, 10.0 M, 1%, 0.063 W, 0402"
R26 R27: "RES, 40.2 k, 1%, 0.063 W, 0402"
R31 R32: "RES, 3.3 k, 5%, 0.063 W, 0402"
TP1 TP2 TP3 TP4 TP5: library part TP_SM_1MM, "1mm Test Point, SMT"
TP6: library part PogoPad, "Pad for Pogo Pin Connector"
U1: "Single Output High PSRR LDO, 200 mA, Fixed 3 V Output, 2.7 to 5.5 V Input, 5-pin SOT-23 (DBV), -40 to 85 degC, Green (RoHS & no Sb/Br)"
U2: "Single Micropower Precision Op Amp"
U3: "Precision Micropower Shunt Voltage Reference, 3-pin SOT-23"
U4: library part RF430CL331H, "The Texas Instruments Dynamic NFC Interface Transponder RF430CL331H is an NFC Tag Type 4 device  that combines a wireless NFC interface and a wired SPI or I2C interface to connect the device to a host."
U5: "LOW INPUT VOLTAGE STEP-UP CONVERTER IN 6 PIN SC-70 PACKAGE, DCK0006A"
U6: library part BMA250, "14 bit, digital, triaxial acceleration sensor with intelligent on-chip motion triggered interrupt controller"
U7: "High-Accuracy, Low-Power, Digital Temperature Sensor With SMBus(TM)/Two-Wire Serial Interface, DRL0006A"
U8: "Low-Power, 2-Channel, 24-Bit Analog Front-End for Biopotential Measurement, PBS0032A"
U9: "Mixed-Signal Microcontrollers, RGC0064B"
Y1: "Crystal, 32.768kHz, 12.5pF, SMD"
ZZ1: library part AssemblyNoteLabel
ZZ2 ZZ3 ZZ4: library part AssemblyNote

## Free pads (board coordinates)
  round 0 hole 3.762 unplated: 0(87.782,88.062)

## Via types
v1: diameter 0.864, hole 0.406, Top Layer to Bottom Layer, 104 vias
v2: diameter 0.5, hole 0.2, Top Layer to Bottom Layer, 13 vias

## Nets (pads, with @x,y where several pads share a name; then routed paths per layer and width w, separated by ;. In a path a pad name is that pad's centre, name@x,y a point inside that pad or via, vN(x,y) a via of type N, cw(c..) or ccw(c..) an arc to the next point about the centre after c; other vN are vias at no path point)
3V: C3.1 C4.1 C35.1 R4.2 R5.2 R15.2 U1.1 U1.3 U5.4 | length 53.6
  Top Layer w0.254: U1.3@93.021,102.55 U1.3@93.099,102.628 ; 94.259,100.178 94.361,100.178 ; C3.1@94.542,102.55 C3.1@94.62,102.628 ; 96.536,106.02 96.536,106.061
  Top Layer w0.54: R15.2@92.888,104.496 96.536,104.496 ; U1.1@93.021,100.65 93.787,100.65 94.259,100.178 ; U1.3@93.021,102.55 C3.1@94.542,102.55 ; 94.361,100.178 97.714,100.178 98.222,100.686 98.222,101.702 95.774,104.15 96.536,104.496 ; C3.1@94.62,102.628 C4.1@95.89,102.628 95.89,104.034 ; U5.4@95.519,109.662 95.519,110.632 95.885,110.998 97.358,110.998 97.866,110.49 ; C35.1@95.723,105.41 96.536,105.41 ; 96.536,106.02 96.536,105.41 ; 96.536,106.061 97.155,106.68 97.155,107.696 97.46,108.001 97.46,110.084 97.866,110.49 ; v1(100.508,113.132) 97.866,110.49 ; v1(103.048,115.672) 105.842,115.672 112.633,122.463 R5.2@112.633,124.816 ; R4.2@112.614,126.365 112.633,126.346 R5.2@112.633,124.861 ; 96.536,104.496 96.536,105.41
  Bottom Layer w0.54: v1(100.508,113.132) v1(103.048,115.672)
ADS1292_DRDY: 9.1 U8.22 U9.16 | length 19.6
  Top Layer w0.254: U8.22@89.32,138.704 89.32,137.039 89.586,136.773 v1(89.586,136.754) ; U9.16@94.494,128.312 v1(95.876,128.312) 96.19,127.998 9.1@96.19,127.356
  Bottom Layer w0.254: v1(89.586,136.754) 89.586,134.602 93.53,130.658 ; 93.53,130.658 v1(95.876,128.312) 95.876,129.448 94.666,130.658 93.53,130.658
ADS1292_ELA: C52.1 J3.2 R30.1 TP4.1 | length 93.4
  Top Layer w1: R30.1@83.638,151.409 83.638,154.733 ; J3.2@87.4,160.454 87.401,157.302 ; C52.1@93.396,152.086 93.396,153.518 92.126,154.788 83.638,154.733 ; TP4.1@145.136,143.358 145.136,153.822 141.656,157.302 88.57,157.302 84.912,157.302 83.638,156.028 83.638,154.733
ADS1292_ERA: C48.1 J3.1 R23.1 TP3.1 | length 92.4
  Top Layer w0.54: R23.1@84.912,151.437 v1@84.912,153.67
  Top Layer w1: TP3.1@28.702,143.358 28.702,153.822 31.293,156.413 78.943,156.413 82.984,160.454 J3.1@84.63,160.454 ; v1(94.615,155.143) 94.666,155.092 C48.1@94.666,152.086
  Bottom Layer w0.54: v1@84.912,153.67 85.725,154.534
  Bottom Layer w1: J3.1@84.63,160.454 84.63,156.873 84.912,156.591 84.912,153.67 v1(84.912,153.314) ; 85.115,155.143 v1(94.615,155.143)
ADS1292_GPIO1: 6.1 U8.26 U9.14 | length 24.5
  Top Layer w0.254: U8.26@91.719,140.603 93.102,140.603 94.617,139.089 94.617,137.976 96.601,135.992 ; U9.14@94.494,127.312 95.218,127.312 96.94,125.59 v1@96.94,125.336 ; 6.1@95.174,131.674 96.044,131.674 v1(96.451,132.08) 96.607,132.236 96.607,135.992
  Bottom Layer w0.254: v1(96.451,132.08) 98.476,130.055 98.476,126.848 v1(96.952,125.324)
ADS1292_GPIO2: 7.1 U8.25 U9.25 | length 20.5
  Top Layer w0.254: U9.25@89.844,128.962 89.844,129.729 ; 89.843,129.73 89.843,131.626 91.059,132.842 95.631,132.842 96.19,133.401 96.19,135.839 94.163,137.866 94.163,138.8 92.86,140.103 U8.25@91.719,140.103 ; 89.843,131.166 7.1@91.364,131.166
ADS1292_IN1N: C46.1 R24.1 R25.2 U8.3 | length 12.8
  Top Layer w0.254: R24.1@89.17,152.202 89.84,152.202 ; U8.3@89.32,145.003 89.32,148.184 89.586,148.45 v1(89.586,148.946) ; 89.395,147.753 90.079,147.753 C46.1@90.764,148.438 ; v1(89.84,153.264) 89.84,152.202 ; R25.2@90.764,152.202 89.84,152.202
  Bottom Layer w0.254: v1(89.586,148.946) 89.586,150.932 89.84,151.186 v1(89.84,153.264)
ADS1292_IN1P: C54.1 R28.1 R29.2 U8.4 | length 9.1
  Top Layer w0.254: U8.4@88.82,145.003 88.82,149.246 89.281,149.708 C54.1@90.764,149.708 ; R28.1@89.17,150.932 89.967,150.932 ; 89.967,149.835 89.967,150.932 ; R29.2@90.764,150.932 89.967,150.932
ADS1292_IN2N: C44.1 R23.2 U8.5 | length 8.7
  Top Layer w0.254: C44.1@86.436,150.291 84.966,150.291 R23.2@84.912,150.237 84.912,149.447 85.268,149.092 86.152,149.092 86.436,148.807 88.32,146.924 U8.5@88.32,145.003
ADS1292_IN2P: C57.1 R30.2 U8.6 | length 9.5
  Top Layer w0.254: C57.1@82.114,150.263 83.584,150.263 R30.2@83.638,150.209 ; R30.2@83.584,150.209 83.584,149.359 84.306,148.638 85.964,148.638 87.82,146.782 U8.6@87.82,145.003
ADS1292_MAIN_CLKSEL: 14.1 U8.14 U9.32 | length 17.1
  Top Layer w0.254: U8.14@85.42,141.103 84.01,141.103 83.344,140.437 83.344,130.658 83.852,130.15 86.03,130.15 ; 14.1@86.03,130.912 86.03,130.15 ; U9.32@86.343,128.962 86.343,129.837 86.03,130.15
ADS1292_RESET: 8.1 U8.15 U9.31 | length 16.9
  Top Layer w0.254: 8.1@85.268,132.944 85.268,131.597 ; U8.15@85.42,140.603 85.4,140.583 84.306,140.583 83.798,140.075 83.798,132.128 84.328,131.597 85.268,131.597 ; U9.31@86.843,128.962 86.843,131.368 86.614,131.597 85.268,131.597
ADS1292_RESP_MODP/IN3N: R26.2 U8.32 | length 2.4
  Top Layer w0.254: U8.32@91.719,143.603 93.387,143.603 93.396,143.612 R26.2@93.396,144.328
ADS1292_RESP_MODP/IN3P: R27.2 TP6.1 U8.31 | length 13.4
  Top Layer w0.254: U8.31@91.719,143.103 93.441,143.103 R27.2@94.666,144.328 97.668,144.328 98.476,145.136 TP6.1@98.476,150.901
ADS1292_RLD: J3.4 R22.2 TP5.1 | length 3.2
  Top Layer w0.254: R22.2@103.14,147.168 104.826,147.168 v1(105.334,146.66)
  Bottom Layer w0.254: v1(105.334,146.66) 105.867,146.126
ADS1292_SPI_CS: 10.1 U8.18 U9.29 | length 14.1
  Top Layer w0.254: 85.36,135.23 10.1@86.538,135.23 ; 87.274,137.328 86.487,136.541 85.868,136.541 85.268,135.941 85.268,134.722 85.522,134.468 87.147,134.468 87.843,133.771 U9.29@87.843,128.962 ; 87.32,137.374 U8.18@87.32,138.704
ADS1292_SPI_DIN: 12.1 U8.19 U9.26 | length 17.3
  Top Layer w0.254: 12.1@81.966,135.23 81.966,135.992 82.22,136.246 v1(82.22,136.5) ; v1@87.82,136.766 U8.19@87.82,138.704 ; U9.26@89.344,128.962 89.344,132.143 v1(89.789,132.588)
  Bottom Layer w0.254: v1(82.22,136.5) v1(87.554,136.5) 87.554,134.823 v1(89.789,132.588)
ADS1292_SPI_DOUT: 11.1 U8.21 U9.27 | length 29.7
  Top Layer w0.254: U9.27@88.843,128.962 88.843,134.074 88.82,134.098 U8.21@88.82,138.704 88.82,140.052 v1(89.586,140.818) ; v1(100,147.93) 100,149.2 11.1@102.032,151.232
  Bottom Layer w0.254: v1(89.586,140.818) 93.65,144.882 96.952,144.882 v1(100,147.93)
ADS1292_SPI_SCLK: 13.1 U8.20 U9.28 | length 21.9
  Top Layer w0.254: 13.1@81.915,147.32 82.677,146.558 84.201,146.558 v1(84.709,146.05) ; v1(87.808,140.31) 88.316,139.802 88.316,133.96 88.343,133.932 U9.28@88.343,128.962
  Bottom Layer w0.254: v1(84.709,146.05) 84.709,143.408 v1(87.808,140.31)
ADS1292_START: 15.1 U8.16 U9.30 | length 15.2
  Top Layer w0.254: 84.252,137.77 15.1@85.014,137.77 ; U8.16@85.42,140.103 84.534,140.103 84.252,139.821 84.252,138.204 84.252,134.722 85.014,133.96 86.792,133.96 87.343,133.408 U9.30@87.343,128.962
ADS1292_VCAP1: C55.1 U8.11 | length 4.6
  Top Layer w0.254: C55.1@80.841,142.603 U8.11@85.42,142.603
ADS1292_VCAP2: C56.1 U8.27 | length 6.8
  Top Layer w0.254: U8.27@91.719,141.103 93.518,141.103 95.071,139.55 95.071,138.022 95.577,137.516 C56.1@96.098,137.516
ADS1292_VREFP: C50.1 C51.1 U8.9 | length 5.9
  Top Layer w0.254: C51.1@81.702,145.58 C51.1@81.407,145.58 81.515,145.472 C50.1@82.931,145.472 83.763,145.472 83.947,145.288 83.947,144.018 84.362,143.603 U8.9@85.42,143.603
ADS_AVCC: C22.1 C23.1 C24.1 C39.1 C40.1 L6.2 R8.2 R24.2 R28.2 U2.5 U8.12 | length 21.4
  Top Layer w0.254: U2.5@76.17,143.8 77.125,143.8 77.343,144.018 v1(77.343,144.78) ; v1(76.581,145.542) 76.63,145.493 77.802,145.493 78.41,146.101 R8.2@78.41,147.33 ; v1(78.359,136.906) 78.723,137.27 79.576,137.27 C23.1@79.634,137.212 ; v1(78.952,141.106) C39.1@80.904,141.106 ; L6.2@79.68,135.522 79.68,137.166 C23.1@79.634,137.212 ; v1(80.696,148.184) C24.1@80.696,150.378 ; C22.1@80.904,137.212 C23.1@79.634,137.212 ; C39.1@81.204,141.164 C40.1@82.474,141.164 83.413,142.103 U8.12@85.42,142.103 ; v1(87.97,149.362) R28.2@87.97,150.932 R24.2@87.97,152.202
ADS_AVSS: C22.2 C23.2 C24.2 C39.2 C40.2 C44.2 C50.2 C51.2 C55.2 C56.2 C57.2 J3.10 J3.11 R3.2 R9.1 R12.1 R25.1 R29.1 U2.2 U3.2 U8.10 U8.13 | length 43.8
  Top Layer w0.254: v1(68.079,123.489) R3.2@69.894,123.489 ; v1(72.684,142.85) U2.2@73.77,142.85 ; R12.1@75.824,148.117 74.854,149.088 74.854,151.74 75.55,152.436 78.802,152.436 80.63,152.436 ; v1@77.902,143.612 v1(78.156,143.612) 78.156,143.205 78.765,142.596 C55.2@79.634,142.596 ; v1(79.883,146.304) 79.883,144.272 80.175,143.98 C51.2@81.407,143.98 81.699,144.272 C50.2@82.931,144.272 82.931,143.51 83.337,143.104 83.947,143.104 U8.10@85.42,143.103 ; C24.2@80.696,151.578 v1(80.696,153.518) ; C22.2@80.904,138.412 79.634,138.412 79.634,139.906 80.904,139.906 82.07,139.906 C40.2@82.301,140.137 ; C57.2@82.114,151.863 v1(82.114,153.496) ; C40.2@82.474,139.964 82.474,140.068 83.767,141.362 ; 83.767,141.373 83.998,141.603 U8.13@85.42,141.603 ; C44.2@86.436,151.891 v1(86.436,153.416) ; R29.1@91.964,150.932 R25.1@91.964,152.202 v1(91.964,153.426) ; C56.2@97.298,137.516 97.298,136.916 v1(97.714,136.5)
  Top Layer w0.54: v1(104.064,135.484) R9.1@104.064,137.17
  other v1: 79.934,139.906
ADS_DVCC: C15.1 C19.1 C20.1 C21.1 C41.1 C42.1 L5.2 L6.1 U8.23 | length 24.7
  Top Layer w0.254: L6.1@79.68,133.972 79.934,133.972 v1(79.934,132.436) ; 89.586,135.484 89.586,134.376 89.84,134.122 C42.1@90.602,134.122 C41.1@91.872,134.122 C19.1@93.142,134.122 C20.1@94.412,134.122 ; 89.602,135.5 90.348,136.246 90.348,137.008 89.82,137.536 U8.23@89.82,138.704 ; C20.1@94.44,134.15 C20.1@94.412,134.122 ; v1(95.377,133.858) 95.377,133.896 95.151,134.122 C20.1@94.412,134.122 ; v1(97.714,132.944) C21.1@97.714,134.122 98.384,133.452 L5.2@99.708,133.452 99.708,134.176 100.762,135.23 100.762,139.294 100,140.056 C15.1@100,141.296
ANTENNA: D1.2 D2.2 R13.2 R14.2 | length 600.2
  Top Layer w0.4: v1(77.14,95.86) 77.902,96.622 98.73,96.622 98.73,73 76.378,73 76.378,97.13 99.238,97.13 99.238,72.492 75.87,72.492 75.87,97.638 99.746,97.638 99.746,71.984 75.311,71.984 75.311,98.044 76.124,98.857 76.124,103.631 76.679,104.055 77.77,104.055 ; v1(77.14,100.178) 77.14,101.702 77.749,102.311 84.506,102.311 84.836,102.641 D2.2@84.836,103.239 ; D1.2@77.77,106.379 77.77,104.055 ; R13.2@79.548,104.055 77.77,104.055 ; 81.072,102.311 R14.2@81.072,104.055
  Bottom Layer w0.4: 75.311,97.079 75.311,71.984 99.746,71.984 99.746,97.638 77.14,97.638 v1(77.14,100.178) ; 75.362,97.13 99.238,97.13 99.238,72.492 75.87,72.492 75.87,96.622 98.73,96.622 98.73,73 76.378,73 76.378,95.098 v1(77.14,95.86)
BMA_AVCC: C16.1 C37.1 L4.1 U6.7 | length 5.4
  Top Layer w0.254: C16.1@74.092,128.647 C37.1@75.362,128.647 ; U6.7@75.095,127.111 75.095,128.38 C37.1@75.362,128.647 ; L4.1@76.848,129.896 76.848,129.045 76.608,128.805 75.52,128.805 C37.1@75.362,128.647
BMA_DVCC: C17.1 C36.1 L3.2 L4.2 U6.1 U6.3 U6.11 | length 28.6
  Top Layer w0.254: U6.11@75.62,125.586 75.62,124.794 75.336,124.511 73.99,124.511 72.72,125.781 72.72,129.616 74.219,131.115 78.08,131.115 78.448,130.747 L4.2@78.448,129.896 78.448,129.096 79.426,128.118 L3.2@80.404,128.118 80.442,128.08 C17.1@80.442,126.224 C36.1@79.172,126.224 78.785,126.611 U6.3@76.645,126.611 ; U6.1@76.645,125.611 76.645,125.158 77.089,124.714 77.953,124.714 78.435,125.197 78.435,126.585
BMA_INT1: U6.5 U9.38 | length 11
  Top Layer w0.254: U6.5@76.12,127.136 76.12,127.657 76.255,127.792 v1(76.73,127.792) ; v1(82.22,126.848) 83.236,125.832 ; 83.256,125.812 U9.38@85.694,125.812
  Bottom Layer w0.254: v1(76.73,127.792) 77.699,127.792 78.717,126.774 79.263,126.774 79.337,126.848 v1(82.22,126.848)
BMA_INT2: U6.6 U9.33 | length 12.2
  Top Layer w0.254: U6.6@75.62,127.136 75.62,127.88 76.192,128.451 77.267,128.451 77.594,128.778 v1(77.673,128.778) ; v1(83.947,129.286) 83.947,128.676 84.312,128.312 U9.33@85.694,128.312
  Bottom Layer w0.254: v1(77.673,128.778) 83.439,128.778 v1(83.947,129.286)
